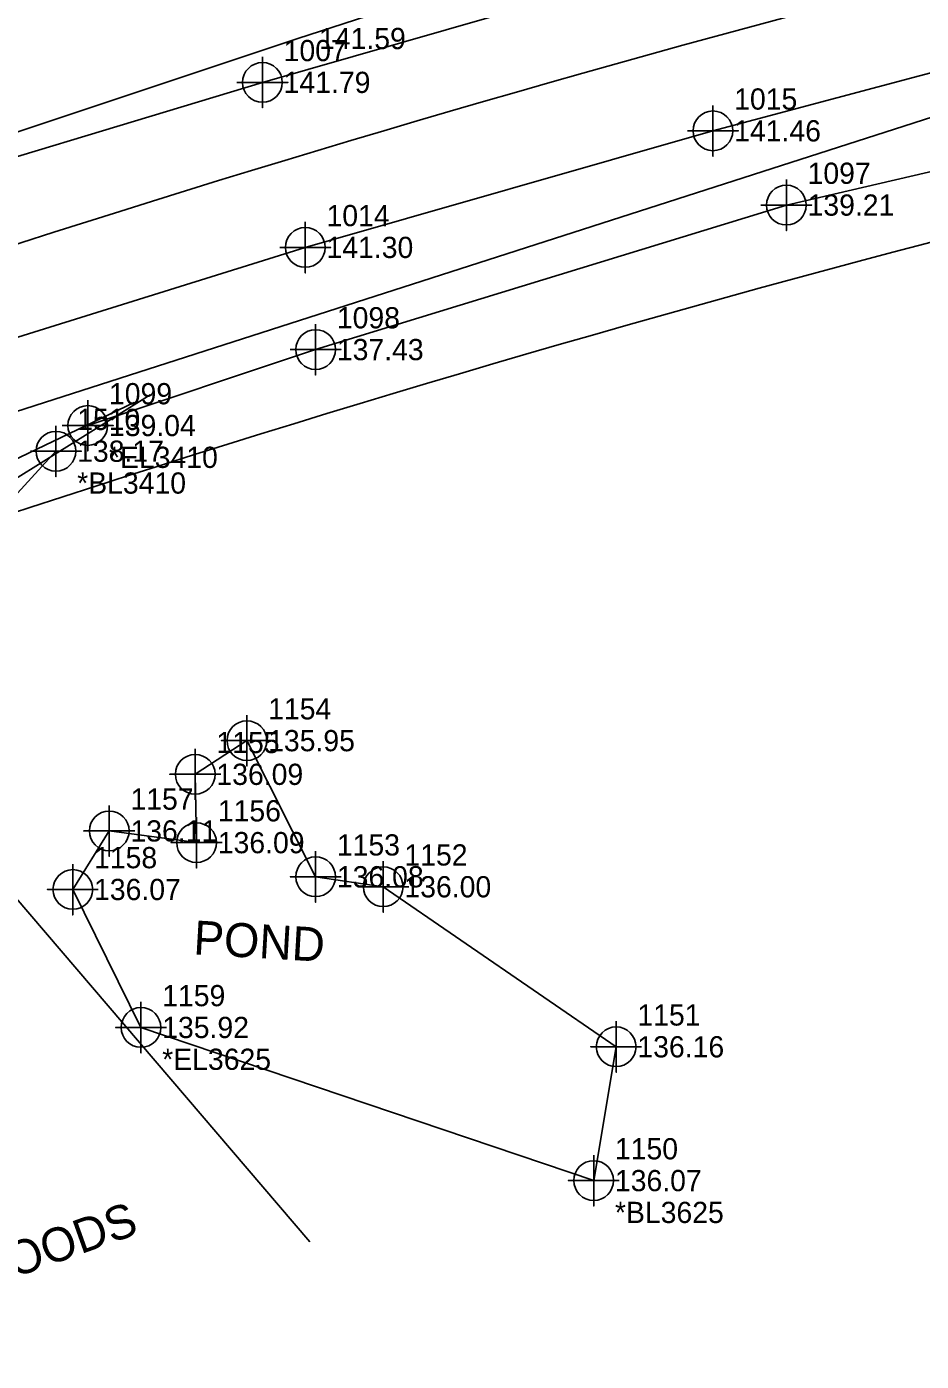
# Model space of a CAD drawing. Extents: x 2248240 to 2249086, y 672625 to 673467.
# Drawn here: x 2248742.5 to 2248847.9, y 672952.2 to 673109.5 of the extents above; entities that cross this region are included whole.
import ezdxf

# ---------------------------------------------------------------- set-up
doc = ezdxf.new("R2010")
doc.units = 0
for name, color, linetype in [('Exist Horizontal Alignment', 7, 'Continuous'), ('Exist Hydro Pool or Reservoir Cogo Comment', 7, 'Continuous'), ('Exist Hydro Pool or Reservoir Cogo Elevation', 7, 'Continuous'), ('Exist Hydro Pool or Reservoir Cogo Number', 7, 'Continuous'), ('Exist Hydro Pool or Reservoir Cogo Point CELL', 7, 'Continuous'), ('Exist Hydro Stream or Body of Water', 7, 'Continuous'), ('Exist Hydro Stream or Body of Water Text', 7, 'Continuous'), ('Exist Other Culture Fence Line', 7, 'Continuous'), ('Exist Other Culture Fence Line Cogo Comment', 7, 'Continuous'), ('Exist Other Culture Fence Line Cogo Elevation', 7, 'Continuous'), ('Exist Other Culture Fence Line Cogo Number', 7, 'Continuous'), ('Exist Other Culture Fence Line Cogo Point CELL', 7, 'Continuous'), ('Exist Right of Way Line', 7, 'Continuous'), ('Exist Roads EOP', 7, 'Continuous'), ('Exist Roads EOP Cogo Elevation', 7, 'Continuous'), ('Exist Roads EOP Cogo Number', 7, 'Continuous'), ('Exist Roads EOP Cogo Point CELL', 7, 'Continuous'), ('Exist Utilities Telephone UG FO SUE LOS B', 7, 'Continuous'), ('Exist Utilities Telephone UG FO SUE LOS B Cogo Elevation', 7, 'Continuous'), ('Exist Utilities Water UG Line SUE LOS C', 7, 'Continuous'), ('Exist Vegetation Woods Line', 7, 'Continuous'), ('Exist Vegetation Woods Line Text', 7, 'Continuous')]:
    doc.layers.add(name, color=color, linetype=linetype)

msp = doc.modelspace()

# ---------------------------------------------------------------- linework, layer by layer
at = {"layer": 'Exist Horizontal Alignment'}
msp.add_arc((2249324.97, 671272.88), 1902.71, 100.37242, 108.2144, dxfattribs=at)
at = {"layer": 'Exist Hydro Pool or Reservoir Cogo Point CELL'}
for points in [[(2248768.47, 673028.36), (2248768.47, 673022.36), (2248768.47, 673025.36), (2248765.47, 673025.36), (2248771.47, 673025.36)], [(2248762.38, 673024.39), (2248762.38, 673018.39), (2248762.38, 673021.39), (2248759.38, 673021.39), (2248765.38, 673021.39)], [(2248752.25, 673017.72), (2248752.25, 673011.72), (2248752.25, 673014.72), (2248749.25, 673014.72), (2248755.25, 673014.72)], [(2248762.54, 673016.34), (2248762.54, 673010.34), (2248762.54, 673013.34), (2248759.54, 673013.34), (2248765.54, 673013.34)], [(2248776.57, 673012.32), (2248776.57, 673006.32), (2248776.57, 673009.32), (2248773.57, 673009.32), (2248779.57, 673009.32)], [(2248747.96, 673010.82), (2248747.96, 673004.82), (2248747.96, 673007.82), (2248744.96, 673007.82), (2248750.96, 673007.82)], [(2248784.53, 673011.14), (2248784.53, 673005.14), (2248784.53, 673008.14), (2248781.53, 673008.14), (2248787.53, 673008.14)], [(2248755.99, 672994.56), (2248755.99, 672988.56), (2248755.99, 672991.56), (2248752.99, 672991.56), (2248758.99, 672991.56)], [(2248811.98, 672992.28), (2248811.98, 672986.28), (2248811.98, 672989.28), (2248808.98, 672989.28), (2248814.98, 672989.28)], [(2248809.33, 672976.51), (2248809.33, 672970.51), (2248809.33, 672973.51), (2248806.33, 672973.51), (2248812.33, 672973.51)]]:
    msp.add_lwpolyline(points, dxfattribs=at)
for centre in [(2248768.47, 673025.36), (2248762.38, 673021.39), (2248752.25, 673014.72), (2248762.54, 673013.34), (2248776.57, 673009.32), (2248747.96, 673007.82), (2248784.53, 673008.14), (2248755.99, 672991.56), (2248811.98, 672989.28), (2248809.33, 672973.51)]:
    msp.add_circle(centre, 2.34, dxfattribs=at)
at = {"layer": 'Exist Hydro Stream or Body of Water'}
msp.add_line((2248755.99, 672991.56), (2248809.33, 672973.51), dxfattribs=at)
msp.add_lwpolyline([(2248809.33, 672973.51), (2248811.98, 672989.28), (2248784.53, 673008.14), (2248776.57, 673009.32), (2248768.47, 673025.36), (2248762.38, 673021.39), (2248762.54, 673013.34), (2248752.25, 673014.72), (2248747.96, 673007.82), (2248755.99, 672991.56)], dxfattribs=at)
at = {"layer": 'Exist Other Culture Fence Line'}
for points in [[(2249071.2, 673137.57), (2249017.67, 673127.8), (2248970.89, 673117.85), (2248920.71, 673107.25), (2248874.48, 673098.31), (2248832.03, 673088.48), (2248776.57, 673071.45), (2248749.72, 673062.5)], [(2248745.97, 673059.47), (2248729.51, 673041.49), (2248719.23, 673025.73), (2248716.58, 673011.24), (2248714.82, 672999.21), (2248713.73, 672988.34), (2248714.28, 672955.99)]]:
    msp.add_lwpolyline(points, dxfattribs=at)
at = {"layer": 'Exist Other Culture Fence Line Cogo Point CELL'}
for points in [[(2248832.03, 673091.48), (2248832.03, 673085.48), (2248832.03, 673088.48), (2248835.03, 673088.48), (2248829.03, 673088.48)], [(2248776.57, 673074.45), (2248776.57, 673068.45), (2248776.57, 673071.45), (2248779.57, 673071.45), (2248773.57, 673071.45)], [(2248749.72, 673065.5), (2248749.72, 673059.5), (2248749.72, 673062.5), (2248752.72, 673062.5), (2248746.72, 673062.5)], [(2248745.97, 673062.47), (2248745.97, 673056.47), (2248745.97, 673059.47), (2248748.97, 673059.47), (2248742.97, 673059.47)]]:
    msp.add_lwpolyline(points, dxfattribs=at)
for centre in [(2248832.03, 673088.48), (2248776.57, 673071.45), (2248749.72, 673062.5), (2248745.97, 673059.47)]:
    msp.add_circle(centre, 2.34, dxfattribs=at)
at = {"layer": 'Exist Right of Way Line'}
for radius, start, end in [(1932.71, 100.3712, 108.35264), (1872.71, 100.37112, 108.35703)]:
    msp.add_arc((2249324.93, 671272.87), radius, start, end, dxfattribs=at)
at = {"layer": 'Exist Roads EOP'}
msp.add_lwpolyline([(2249065.54, 673169.89), (2249016.36, 673161.46), (2248966.2, 673152.17), (2248916.42, 673141.64), (2248867.99, 673130.25), (2248818.93, 673116.91), (2248770.3, 673102.94), (2248722.94, 673088.63), (2248715.63, 673086.15), (2248700.51, 673081.75), (2248707.22, 673061.33), (2248721.04, 673066.46), (2248728.59, 673068.92), (2248775.35, 673083.49), (2248823.38, 673097.23), (2248872.06, 673110.21), (2248920.2, 673121.59), (2248969.29, 673132.45), (2249018.22, 673141.67), (2249067.64, 673149.87)], dxfattribs=at)
at = {"layer": 'Exist Roads EOP Cogo Point CELL'}
for points in [[(2248770.3, 673105.94), (2248770.3, 673099.94), (2248770.3, 673102.94), (2248773.3, 673102.94), (2248767.3, 673102.94)], [(2248823.38, 673100.23), (2248823.38, 673094.23), (2248823.38, 673097.23), (2248826.38, 673097.23), (2248820.38, 673097.23)], [(2248775.35, 673086.49), (2248775.35, 673080.49), (2248775.35, 673083.49), (2248778.35, 673083.49), (2248772.35, 673083.49)]]:
    msp.add_lwpolyline(points, dxfattribs=at)
for centre in [(2248770.3, 673102.94), (2248823.38, 673097.23), (2248775.35, 673083.49)]:
    msp.add_circle(centre, 2.34, dxfattribs=at)
at = {"layer": 'Exist Utilities Telephone UG FO SUE LOS B'}
msp.add_lwpolyline([(2248704.39, 673102.35), (2248714.18, 673090.62), (2248722.71, 673090.87), (2248774.47, 673108.11), (2248816.35, 673121.7), (2248873.5, 673136.04), (2248938.12, 673150.39)], dxfattribs=at)
at = {"layer": 'Exist Utilities Water UG Line SUE LOS C'}
msp.add_line((2248530.3, 672996.29), (2248853.08, 673100.11), dxfattribs=at)
at = {"layer": 'Exist Vegetation Woods Line'}
for points in [[(2248757.06, 673066.12), (2248728.33, 673048.2), (2248728.33, 673021.93), (2248775.9, 672966.31)], [(2248709.88, 672952.21), (2248697.88, 673003.42), (2248696.7, 673038.35), (2248715.82, 673046.34), (2248755.17, 673065.23)]]:
    msp.add_lwpolyline(points, dxfattribs=at)

# ---------------------------------------------------------------- texts
at = {"layer": 'Exist Hydro Pool or Reservoir Cogo Comment'}
for s, p in [('*EL3625', (2248758.49, 672986.56)), ('*BL3625', (2248811.83, 672968.51))]:
    msp.add_text(s, height=2.5, dxfattribs=at).set_placement(p)
at = {"layer": 'Exist Hydro Pool or Reservoir Cogo Elevation'}
for s, p in [('135.95', (2248770.97, 673024.11)), ('136.09', (2248764.88, 673020.14)), ('136.11', (2248754.75, 673013.47)), ('136.09', (2248765.04, 673012.09)), ('136.07', (2248750.46, 673006.57)), ('136.08', (2248779.07, 673008.07)), ('136.00', (2248787.03, 673006.89)), ('135.92', (2248758.49, 672990.31)), ('136.16', (2248814.48, 672988.03)), ('136.07', (2248811.83, 672972.26))]:
    msp.add_text(s, height=2.5, dxfattribs=at).set_placement(p)
at = {"layer": 'Exist Hydro Pool or Reservoir Cogo Number'}
for s, p in [('1154', (2248770.97, 673027.86)), ('1155', (2248764.88, 673023.89)), ('1157', (2248754.75, 673017.22)), ('1156', (2248765.04, 673015.84)), ('1153', (2248779.07, 673011.82)), ('1158', (2248750.46, 673010.32)), ('1152', (2248787.03, 673010.64)), ('1159', (2248758.49, 672994.06)), ('1151', (2248814.48, 672991.78)), ('1150', (2248811.83, 672976.01))]:
    msp.add_text(s, height=2.5, dxfattribs=at).set_placement(p)
at = {"layer": 'Exist Hydro Stream or Body of Water Text'}
msp.add_text('POND', height=4, rotation=356.6944, dxfattribs=at).set_placement((2248762.11, 673000.18))
at = {"layer": 'Exist Other Culture Fence Line Cogo Comment'}
for s, p in [('*EL3410', (2248752.22, 673057.5)), ('*BL3410', (2248748.47, 673054.47))]:
    msp.add_text(s, height=2.5, dxfattribs=at).set_placement(p)
at = {"layer": 'Exist Other Culture Fence Line Cogo Elevation'}
for s, p in [('139.21', (2248834.53, 673087.23)), ('137.43', (2248779.07, 673070.2)), ('139.04', (2248752.22, 673061.25)), ('138.17', (2248748.47, 673058.22))]:
    msp.add_text(s, height=2.5, dxfattribs=at).set_placement(p)
at = {"layer": 'Exist Other Culture Fence Line Cogo Number'}
for s, p in [('1097', (2248834.53, 673090.98)), ('1098', (2248779.07, 673073.95)), ('1099', (2248752.22, 673065)), ('1510', (2248748.47, 673061.97))]:
    msp.add_text(s, height=2.5, dxfattribs=at).set_placement(p)
at = {"layer": 'Exist Roads EOP Cogo Elevation'}
for s, p in [('141.79', (2248772.8, 673101.69)), ('141.46', (2248825.88, 673095.98)), ('141.30', (2248777.85, 673082.24))]:
    msp.add_text(s, height=2.5, dxfattribs=at).set_placement(p)
at = {"layer": 'Exist Roads EOP Cogo Number'}
for s, p in [('1007', (2248772.8, 673105.44)), ('1015', (2248825.88, 673099.73)), ('1014', (2248777.85, 673085.99))]:
    msp.add_text(s, height=2.5, dxfattribs=at).set_placement(p)
at = {"layer": 'Exist Utilities Telephone UG FO SUE LOS B Cogo Elevation'}
msp.add_text('141.59', height=2.5, dxfattribs=at).set_placement((2248776.97, 673106.86))
msp.add_text('141.59', height=2.5, dxfattribs=at).set_placement((2248776.97, 673106.86))
at = {"layer": 'Exist Vegetation Woods Line Text'}
msp.add_text('WOODS', height=4, rotation=19.6529, dxfattribs=at).set_placement((2248736.29, 672960.32))

doc.saveas('drawing.dxf')
